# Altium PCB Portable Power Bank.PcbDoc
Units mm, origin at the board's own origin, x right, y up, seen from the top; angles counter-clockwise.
Board outline 51 x 35 mm, 2 copper layers (Top Layer, Bottom Layer); 57 components, 43 nets, 200 pads, 71 vias.
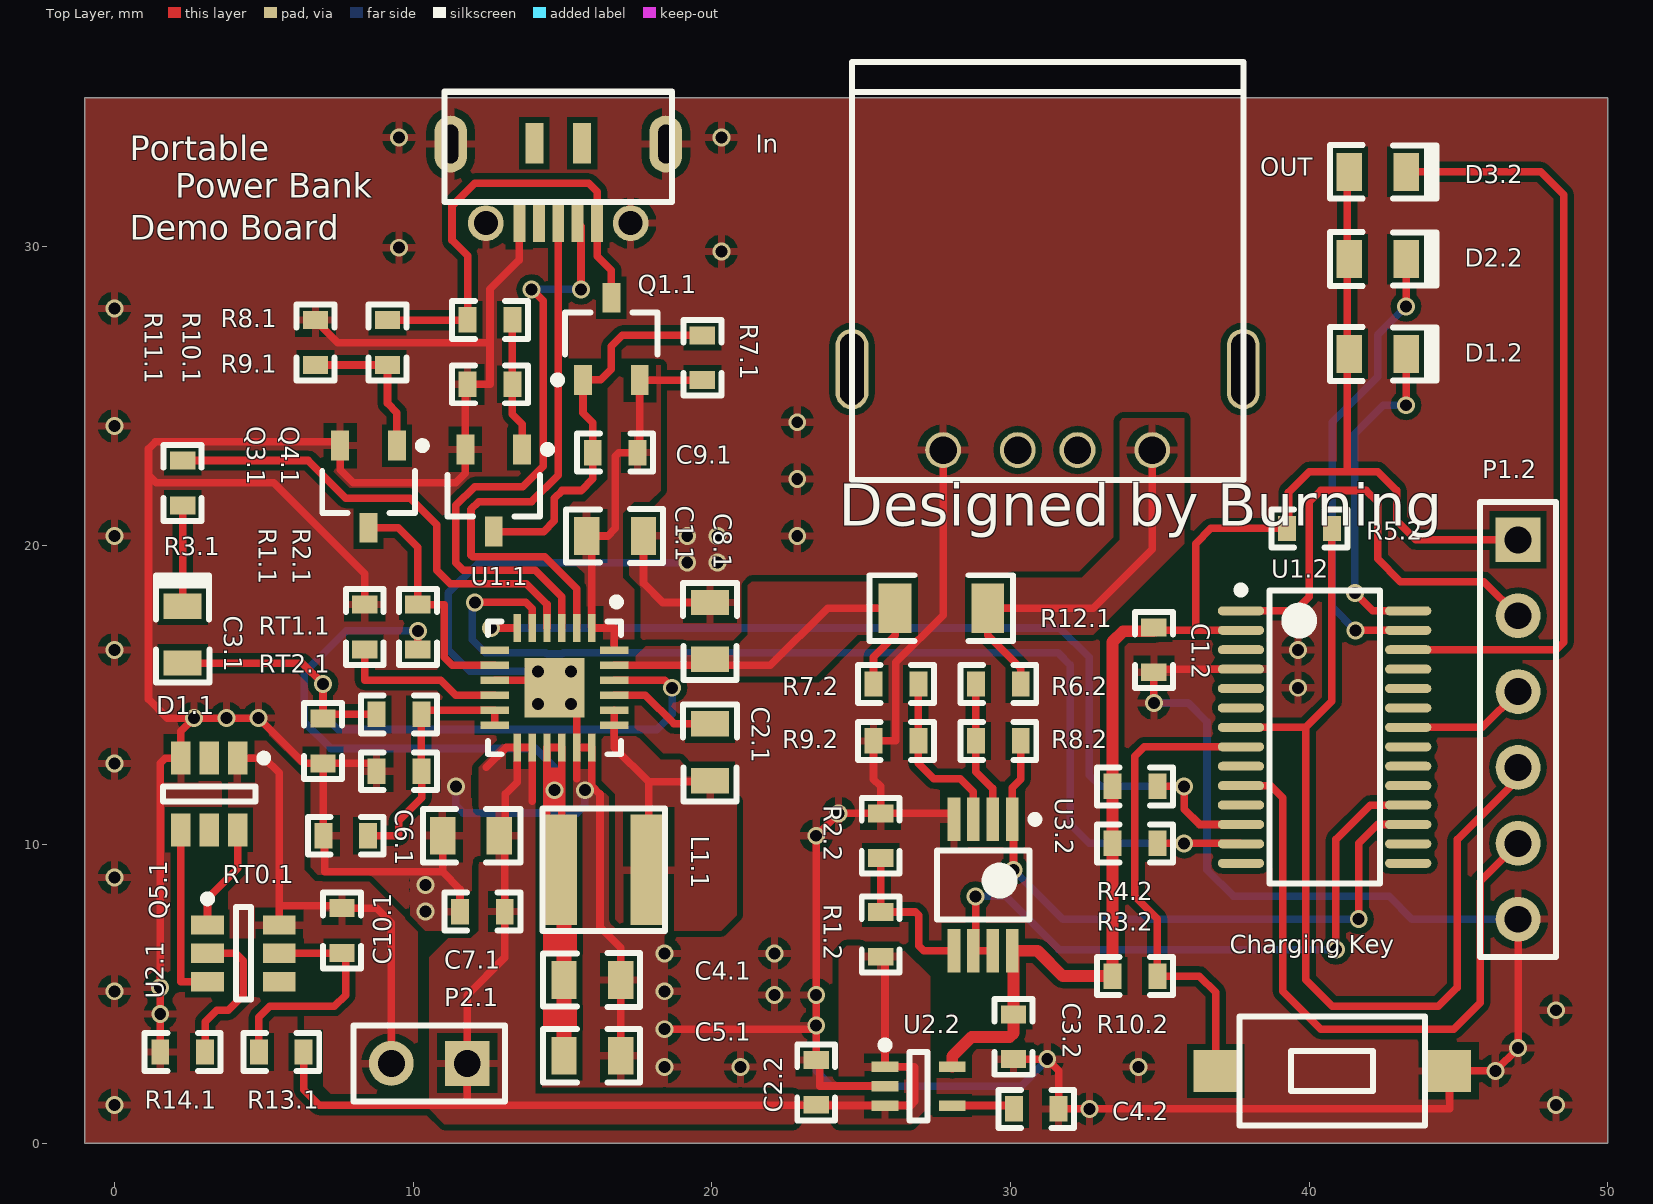
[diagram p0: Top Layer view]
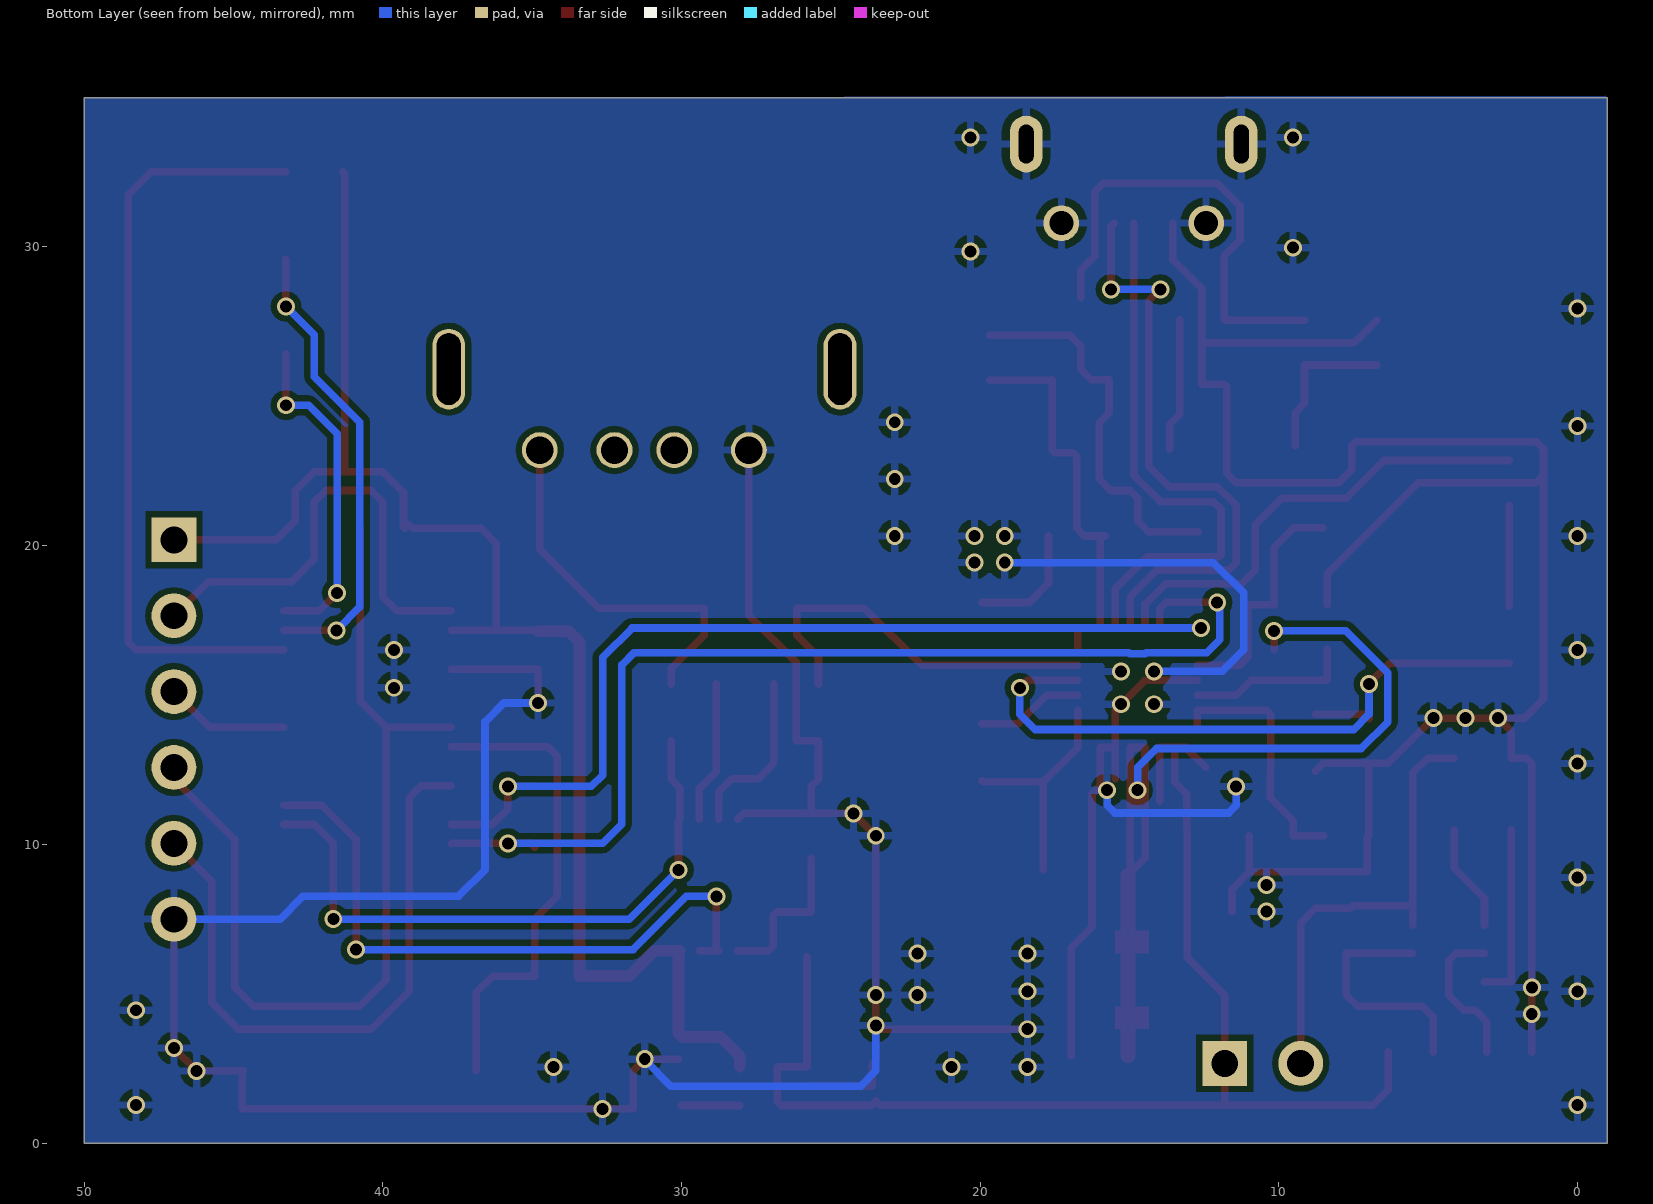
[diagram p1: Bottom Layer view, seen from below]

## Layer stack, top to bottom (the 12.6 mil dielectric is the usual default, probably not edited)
Top Solder: solder mask 0.0102, Solder Resist, Dk 3.5
Top Layer: signal copper 0.0356
Dielectric 1: dielectric 0.32, FR-4, Dk 4.8
Bottom Layer: signal copper 0.0356
Bottom Solder: solder mask 0.0102, Solder Resist, Dk 3.5

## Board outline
-1,0 -1,35 50,35 50,0

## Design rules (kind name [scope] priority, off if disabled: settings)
Clearance [All] p1: gap=0.2
PolygonConnect [All] p1: connectstyle=Relief reliefconductorwidth=0.254 reliefentries=4 polygonreliefangle="90 Angle" airgapwidth=0.254
RoutingVias [All] p1: holewidth=0.711 width=1.27 viastyle="Through Hole" minholewidth=0.711 minwidth=1.27 maxholewidth=0.711 maxwidth=1.27
SolderMaskExpansion [All] p1: expansion=0.102
Width [All] p1: maxlimit=1 minlimit=0.254 preferedwidth=0.254
30 further rules are at their usual default settings.

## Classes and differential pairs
component class "Portable Power Source": C1.1 C2.1 C3.1 C4.1 C5.1 C6.1 C7.1 C8.1 C9.1 C10.1 D1.1 In L1.1 P2.1 Q1.1 Q3.1 Q4.1 Q5.1 R1.1 R2.1 R3.1 R7.1 R8.1 R9.1 R10.1 R11.1 R12.1 R13.1 R14.1 RT0.1 RT1.1 RT2.1 U1.1 U2.1

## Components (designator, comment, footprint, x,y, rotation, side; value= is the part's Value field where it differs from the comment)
C1.1 "0603" D0805 16.764,20.32 r180 top (schematic designator C1)
C1.2 "0603" D0603 34.798,16.51 r90 top (schematic designator C1)
C2.1 "0603" D0805 19.939,13.081 r270 top (schematic designator C2)
C2.2 "0603" D0603 23.495,2.032 r270 top (schematic designator C2)
C3.1 "0603" D0603 6.985,13.462 r90 top (schematic designator C3)
C3.2 "0603" D0603 30.099,3.556 r90 top (schematic designator C3)
C4.1 "0805" D0805 16.002,5.461 r180 top (schematic designator C4)
C4.2 "0603" D0603 30.861,1.143 r180 top (schematic designator C4)
C5.1 "0805" D0805 16.002,2.921 r180 top (schematic designator C5)
C6.1 "0805" D0805 11.938,10.287 r0 top (schematic designator C6)
C7.1 "0603" D0603 12.319,7.747 r0 top (schematic designator C7)
C8.1 "0805" D0805 19.939,17.145 r270 top (schematic designator C8)
C9.1 "0603" D0603 16.764,23.114 r180 top (schematic designator C9)
C10.1 "0603" D0603 7.62,7.112 r270 top (schematic designator C10)
"Charging Key" "Charging Key" SW_A 40.767,2.413 r0 top (schematic designator S1)
D1.1 "0603/0805" D0805_Diode 2.286,17.018 r90 top (schematic designator D1)
D1.2 "0603/0805" D0805_Diode 42.291,26.416 r0 top (schematic designator D1)
D2.2 "0603/0805" D0805_Diode 42.291,29.591 r0 top (schematic designator D2)
D3.2 "0603/0805" D0805_Diode 42.291,32.512 r0 top (schematic designator D3)
In "Power" Micro.Horn 14.859,32.131 r0 top (schematic designator P1)
L1.1 "Inductor" INDUCTOR.4040 16.383,9.144 r180 top (schematic designator L1)
OUT "USB Female" "USB Female" 31.242,25.908 r180 top (schematic designator P0)
P1.2 "BSL Program Interface" HDR1X6 46.99,20.193 r270 top (schematic designator P1)
P2.1 "Battery" HDR1X2 11.811,2.667 r180 top (schematic designator P2)
Q1.1 "AO3401" SOT23 16.637,26.924 r90 top (schematic designator Q1)
Q3.1 "Si2312" SOT23 8.509,21.971 r270 top (schematic designator Q3)
Q4.1 "Si2312" SOT23 12.7,21.844 r270 top (schematic designator Q4)
Q5.1 "FS8205" SOT23-6_N 3.175,11.684 r270 top (schematic designator Q5)
R1.1 "0603" D0603 8.382,17.272 r270 top (schematic designator R1)
R1.2 "0603" D0603 25.654,6.985 r270 top (schematic designator R1)
R2.1 "0603" D0603 10.16,17.272 r270 top (schematic designator R2)
R2.2 "0603" D0603 25.654,10.287 r270 top (schematic designator R2)
R3.1 "0603" D0603 2.286,22.098 r270 top (schematic designator R3)
R3.2 "0603" D0603 34.163,10.033 r180 top (schematic designator R3)
R4.2 "0603" D0603 34.163,11.938 r180 top (schematic designator R4)
R5.2 "0603" D0603 40.005,20.574 r0 top (schematic designator R5)
R6.2 "0603" D0603 29.591,15.367 r0 top (schematic designator R6)
R7.1 "0603" D0603 19.685,26.289 r90 top (schematic designator R7)
R7.2 "0603" D0603 26.162,15.367 r0 top (schematic designator R7)
R8.1 "0603" D0603 12.573,27.559 r180 top (schematic designator R8)
R8.2 "0603" D0603 29.591,13.462 r0 top (schematic designator R8)
R9.1 "0603" D0603 12.573,25.4 r0 top (schematic designator R9)
R9.2 "0603" D0603 26.162,13.462 r0 top (schematic designator R9)
R10.1 "0603" D0603 9.144,26.797 r90 top (schematic designator R10)
R10.2 "0603" D0603 34.163,5.588 r0 top (schematic designator R10)
R11.1 "0603" D0603 6.731,26.797 r270 top (schematic designator R11)
R12.1 "2512" D1206 27.686,17.907 r180 top (schematic designator R12)
R13.1 "0603" D0603 5.588,3.048 r180 top (schematic designator R13)
R14.1 "0603" D0603 2.286,3.048 r0 top (schematic designator R14)
RT0.1 "0603" D0603 7.747,10.287 r0 top (schematic designator RT0)
RT1.1 "0603" D0603 9.525,14.351 r180 top (schematic designator RT1)
RT2.1 "0603" D0603 9.525,12.446 r0 top (schematic designator RT2)
U1.1 "bq24195" QFN24 14.732,15.24 r270 top (schematic designator U1)
U1.2 "MSP430F21x2" TSSOP28 40.513,13.589 r0 top (schematic designator U1)
U2.1 "DW01" SOT23-6_N 4.318,6.35 r0 top (schematic designator U2)
U2.2 "RT9193" SC70-5 26.924,1.905 r0 top (schematic designator U2)
U3.2 "TLV342" TSSOP8 29.083,8.636 r270 top (schematic designator U3)

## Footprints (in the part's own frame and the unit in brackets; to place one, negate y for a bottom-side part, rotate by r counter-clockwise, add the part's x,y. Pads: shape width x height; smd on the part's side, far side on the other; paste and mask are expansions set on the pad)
D0603 [mm] "D0603"
  rect 0.6x0.85 smd: 1(-0.75,0) 2(0.75,0)
  silkscreen extent -1.27,-0.64 1.27,0.64, body extent -0.8,-0.4 0.8,0.4, height 0.5
D0805 [mm] "D0805"
  rect 0.85x1.27 smd: 1(-0.95,0) 2(0.95,0)
  silkscreen extent -1.6,-0.9 1.65,0.9, body extent -1,-0.64 1,0.64, height 1.25
D0805_Diode [mm] "D0805 Diode"
  rect 0.85x1.27 smd: 1(-0.95,0) 2(0.95,0)
  silkscreen extent -1.6,-0.99 1.97,0.99, body extent -1,-0.64 1,0.64, height 1.25
D1206 [mm] "D1206"
  rect 1.1x1.65 smd: 1(-1.55,0) 2(1.55,0)
  silkscreen extent -2.4,-1.1 2.4,1.1, body extent -1.6,-0.8 1.6,0.8, height 1.1
HDR1X2 [mm] "Connector; Header; 2 Position"
  rect 1.5x1.5 hole 0.9: 1(0,0)
  round 1.5 hole 0.9: 2(2.54,0)
  silkscreen extent -1.27,-1.27 3.81,1.27
HDR1X6 [mm] "Connector; Header; 6 Position"
  rect 1.5x1.5 hole 0.9: 1(0,0)
  round 1.5 hole 0.9: 2(2.54,0) 3(5.08,0) 4(7.62,0) 5(10.16,0) 6(12.7,0)
  silkscreen extent -1.27,-1.27 13.97,1.27
INDUCTOR.4040 [mm]
  rect 1.2x3.7 smd mask+0.05: 1(-1.5,0) 2(1.5,0)
  silkscreen extent -2.05,-2.05 2.05,2.05
Micro.Horn [mm]
  oval 1.1x1.9 hole 0.5 slot 1.3 at 90 deg: 0(-3.6,1.313) 0(3.6,1.313)
  round 1.2 hole 0.8: 0(-2.425,-1.337) 0(2.425,-1.337)
  rect 0.6x1.35 smd: 0(-0.8,1.338) 0(0.8,1.338)
  rect 0.4x1.25 smd: 1(1.3,-1.337) 2(0.65,-1.337) 3(0,-1.337) 4(-0.65,-1.337) 5(-1.3,-1.337)
  silkscreen extent -3.81,-0.64 3.81,3.06
QFN24 [mm] "QFN, 24-Leads, Body 4.00x4.00mm, Pitch 0.50mm, Thermal Pad 2.70x2.70mm, IPC Low Density"
  rect 0.95x0.25 smd: 1(-2,1.25) 2(-2,0.75) 3(-2,0.25) 4(-2,-0.25) 5(-2,-0.75) 6(-2,-1.25) 13(2,-1.25) 14(2,-0.75) 15(2,-0.25) 16(2,0.25) 17(2,0.75) 18(2,1.25)
  rect 0.25x0.95 smd: 7(-1.25,-2) 8(-0.75,-2) 9(-0.25,-2) 10(0.25,-2) 11(0.75,-2) 12(1.25,-2) 19(1.25,2) 20(0.75,2) 21(0.25,2) 22(-0.25,2) 23(-0.75,2) 24(-1.25,2)
  rect 2x2 smd: 25(0,0)
  silkscreen extent -3,-2.22 2.22,2.23, body extent -2.08,-2.07 2.07,2.08, height 1
SC70-5 [mm] "SC70, 5-Leads, Body 2.03x2.13mm, Pitch 0.65mm, IPC Medium Density"
  rect 0.9x0.35 smd: 1(-1.125,0.65) 2(-1.125,0) 3(-1.125,-0.65) 4(1.125,-0.65) 5(1.125,0.65)
  silkscreen extent -1.25,-1.15 0.3,1.5, body extent -0.67,-1.12 0.67,1.13, height 1.1
SOT23 [mm] "SOT23, 3-Leads, Body 2.90x2.80mm, Pitch 0.95mm, IPC Medium Density"
  rect 1x0.6 smd: 1(-1.375,0.95) 2(1.375,0) 3(-1.375,-0.95)
  silkscreen extent -1.5,-1.55 0.87,1.92, body extent -0.88,-1.52 0.87,1.53, height 1.45
SOT23-6_N [mm] "SOT23, 6-Leads, Body 2.9x1.6mm, Pitch 0.95mm, Lead Span 2.7mm, IPC Medium Density"
  rect 1.1x0.65 smd: 1(-1.2,0.95) 2(-1.2,0) 3(-1.2,-0.95) 4(1.2,-0.95) 5(1.2,0) 6(1.2,0.95)
  silkscreen extent -1.32,-1.55 0.25,1.95, body extent -0.9,-1.55 0.9,1.55, height 1.45
SW_A [mm] "SMA Switch"
  rect 1.5x1.4 smd mask+0.05: 1(-3.9,0) 2(3.9,0)
  silkscreen extent -3.1,-1.83 3.1,1.83, body extent -3.1,-1.83 3.1,1.83, height 2
TSSOP8 [mm] "TSOP, 8-Leads, Body 3.00x3.00mm, Pitch 0.65mm, IPC Medium Density"
  rect 1.45x0.42 smd: 1(-2.2,0.975) 2(-2.2,0.325) 3(-2.2,-0.325) 4(-2.2,-0.975) 5(2.2,-0.975) 6(2.2,-0.325) 7(2.2,0.325) 8(2.2,0.975)
  silkscreen extent -2.32,-1.55 1.15,1.86, body extent -1.55,-1.55 1.55,1.55, height 1.1
TSSOP28 [mm] "TSOP, 28-Leads, Body 9.70x4.40mm, Pitch 0.65mm, IPC High Density"
  oval 1.55x0.3 smd: 1(-2.8,4.225) 2(-2.8,3.575) 3(-2.8,2.925) 4(-2.8,2.275) 5(-2.8,1.625) 6(-2.8,0.975) 7(-2.8,0.325) 8(-2.8,-0.325) 9(-2.8,-0.975) 10(-2.8,-1.625) 11(-2.8,-2.275) 12(-2.8,-2.925) 13(-2.8,-3.575) 14(-2.8,-4.225) 15(2.8,-4.225) 16(2.8,-3.575) 17(2.8,-2.925) 18(2.8,-2.275) 19(2.8,-1.625) 20(2.8,-0.975) 21(2.8,-0.325) 22(2.8,0.325) 23(2.8,0.975) 24(2.8,1.625) 25(2.8,2.275) 26(2.8,2.925) 27(2.8,3.575) 28(2.8,4.225)
  silkscreen extent -2.92,-4.9 1.85,5.05, body extent -2.25,-4.9 2.25,4.9, height 1.2
"USB Female" [mm]
  round 1.2 hole 0.92 mask+0.05: 1(-3.5,2.71) 2(-1,2.71) 3(1,2.71) 4(3.5,2.71)
  oval 1.1x2.7 hole 0.8 slot 2.4 at 90 deg mask+0.05: 5(-6.55,0) 5(6.55,0)
  silkscreen extent -6.55,-10.28 6.55,3.71

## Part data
C1.1 C1.2 C2.1 C2.2 C3.1 C3.2 C4.1 C4.2 C5.1 C6.1 C7.1 C8.1 C9.1 C10.1: library part Cap, "Capacitor"
"Charging Key": library part SW-PB, "Switch"
D1.1 D1.2 D2.2 D3.2: library part LED0, "Typical INFRARED GaAs LED"
In: library part "Micro USB Horn", "MIcro USB Connector Horn"
P1.2: library part "Header 6", "Header, 6-Pin"
P2.1: library part "Header 2", "Header, 2-Pin"
Q1.1: "AO3401 P-Channel MOSFET"
Q3.1 Q4.1: "SI2312 N-Channel MOSFEt"
Q5.1: "FS8205 Dual MOS"
R1.1 R1.2 R2.1 R2.2 R3.1 R3.2 R4.2 R5.2 R6.2 R7.1 R7.2 R8.1 R8.2 R9.1 R9.2 R10.1 R10.2 R11.1 R12.1 R13.1 R14.1 RT0.1 RT1.1 RT2.1: library part Res1, "Resistor"
U1.1: "A Battery charger manager published by Ti"
U1.2: library part MSP430F21x2_PW, "MSP430F21x2_PW"
U2.1: "Battery Protector"
U2.2: "3V3 Voltage Regulator"
U3.2: library part LPV358, "LPV358 Op Amp"

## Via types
v1: diameter 0.6, hole 0.4, Top Layer to Bottom Layer, 71 vias

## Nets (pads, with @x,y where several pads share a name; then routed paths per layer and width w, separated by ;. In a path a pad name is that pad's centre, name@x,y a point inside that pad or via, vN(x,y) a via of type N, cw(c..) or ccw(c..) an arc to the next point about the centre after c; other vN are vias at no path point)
3V3: C1.2.2 C3.2.2 D1.2.1 D2.2.1 D3.2.1 P1.2.1 R3.2.2 R4.2.2 R5.2.1 R10.2.1 U1.2.2 U2.2.5 U3.2.8 | length 51.7
  Top Layer w0.254: U3.2.8 U3.2.8@30.099,6.395 ; C1.2.2@34.798,17.133 34.829,17.164 36.195,17.164 ; U1.2.2 36.195,17.164 ; R5.2.1@39.128,20.701 39.001,20.574 36.703,20.574 36.195,20.066 36.195,17.164 ; R5.2.1 39.306,20.626 39.306,21.78 40.005,22.479 41.275,22.479 ; D3.2.1 41.275,32.446 41.275,22.479 ; P1.2.1 43.561,20.193 42.926,20.828 42.926,21.844 42.291,22.479 41.275,22.479
  Top Layer w0.4: U2.2.5 28.049,2.903 28.702,3.556 29.972,3.556 30.099,3.683 C3.2.2 U3.2.8@30.099,6.395 ; U3.2.8 30.902,6.436 31.75,5.588 R10.2.1 R4.2.2 33.413,16.776 33.77,17.133 C1.2.2@34.798,17.133
ADC_B: U1.2.18 U3.2.6 U3.2.7 | length 21.9
  Top Layer w0.254: v1(28.829,8.255) 28.829,6.507 U3.2.6 U3.2.7 ; v1(40.894,6.477) 40.894,10.16 42.048,11.314 U1.2.18
  Bottom Layer w0.254: v1(28.829,8.255) 29.845,8.255 31.623,6.477 v1(40.894,6.477)
ADC_L: R8.2.2 U1.2.17 U3.2.1 | length 21.2
  Top Layer w0.254: v1(30.099,9.144) 30.099,10.795 U3.2.1 30.058,11.897 30.341,12.18 R8.2.2 ; v1(41.656,7.493) 41.656,10.033 42.287,10.664 U1.2.17
  Bottom Layer w0.254: v1(30.099,9.144) 31.75,7.493 v1(41.656,7.493)
BAT: C2.2.2 C6.1.2 C7.1.2 P2.1.1 R1.2.2 R13.1.1 U1.1.13 U1.1.14 U2.2.1 U2.2.3 | length 44.2
  Top Layer w0.254: R13.1.1 6.338,1.79 6.858,1.27 11.811,1.27 ; 12.446,12.573 13.113,13.24 U1.1.13 ; 13.982,11.442 U1.1.14 U1.1.13 ; R1.2.2@25.799,6.235 U2.2.1 26.782,2.555 26.797,2.54 26.797,1.397 26.655,1.255 U2.2.3 23.649,1.255 23.495,1.409 23.356,1.27 11.811,1.27 ; 11.811,1.27 P2.1.1 11.811,4.953 13.069,6.211 C7.1.2 13.069,10.468 13.081,10.48 13.081,11.684 13.482,12.085 U1.1.13
D+: In.3 U1.1.2 | length 18.7
  Top Layer w0.254: In.3 14.859,22.359 13.963,21.463 12.192,21.463 11.938,21.209 11.938,19.685 11.991,19.632 14.404,19.632 15.482,18.554 U1.1.2
D-: In.2 U1.1.3 | length 20.4
  Top Layer w0.254: v1(13.97,28.575) 14.351,28.194 14.351,22.658 13.664,21.971 12.058,21.971 11.43,21.343 11.43,19.431 11.683,19.178 14.096,19.178 14.982,18.292 U1.1.3 ; In.2 15.621,30.681 v1(15.621,28.575)
  Bottom Layer w0.254: v1(13.97,28.575) v1(15.621,28.575)
GND: "Charging Key.2" C1.1.1 C1.2.1 C2.2.1 C3.1.1 C3.2.1 C4.1.1 C4.2.1 C5.1.1 C6.1.1 C7.1.1 C8.1.1 In.0@11.259,33.444 In.0@12.434,30.794 In.0@17.284,30.794 In.0@18.459,33.444 In.5 OUT.4 P1.2.6 Q3.1.3 Q4.1.3 Q5.1.3 R1.1.1 R2.2.1 R9.1.1 R9.2.1 R11.1.1 R14.1.1 RT0.1.1 RT2.1.1 U1.1.9 U1.1.17 U1.1.18 U1.1.25 U1.2.4 U2.2.2 U3.2.4 | length 206.9
  Top Layer w0.254: R14.1.1 1.536,12.712 1.708,12.884 Q5.1.3 2.225,13.782 v1(2.667,14.224) ; R11.1.1 7.481,26.797 12.573,26.797 ; R1.1.1 8.382,19.05 5.334,22.098 1.397,22.098 1.143,22.352 ; RT2.1.1 8.509,12.712 C3.1.1 ; C6.1.1 10.988,9.078 ; C7.1.1 11.569,8.497 10.988,9.078 ; U1.1.9 14.482,15.49 U1.1.25 v1(15.282,14.69) ; In.5 13.559,29.561 12.573,28.575 12.573,26.797 ; 15.482,12.204 U1.1.17 ; U1.1.25@15.482,14.49 U1.1.17 ; C5.1.1 C4.1.1 16.952,6.543 16.256,7.239 16.256,11.684 15.982,11.958 U1.1.18 U1.1.17 ; C1.1.1 17.714,18.735 18.354,18.095 C8.1.1 ; v1(18.415,3.81) 23.368,3.81 v1(23.495,3.937) ; U2.2.2 25.799,1.909 23.618,1.909 23.618,2.659 C2.2.1 v1(23.495,3.937) ; OUT.4 27.742,17.676 26.162,16.096 26.162,13.462 R9.2.1 25.412,12.18 25.654,11.938 R2.2.1 ; U3.2.4 27.907,11.037 R2.2.1 ; C3.2.1 v1(31.23,2.806) 31.611,2.425 C4.2.1 v1(32.639,1.143) 44.704,1.143 44.704,2.376 44.667,2.413 v1(46.228,2.413) v1(46.99,3.175) P1.2.6 ; v1(34.798,14.732) C1.2.1 ; C1.2.1@34.798,15.864 U1.2.4 ; 1.143,22.352 1.143,14.859 1.778,14.224 v1(2.667,14.224) ; 1.143,22.352 1.143,23.241 1.377,23.475 7.43,23.475 Q3.1.3 7.559,22.54 8.001,22.098 11.43,22.098 11.75,22.418 Q4.1.3 11.75,25.327 R9.1.1 12.573,25.4 12.573,26.797 ; v1(2.667,14.224) v1(3.746,14.224) v1(4.826,14.224) 6.338,12.712 C3.1.1 ; C3.1.1 6.997,12.7 RT0.1.1 7.046,10.238 7.046,9.078 10.988,9.078 ; v1(23.495,3.937) v1(23.495,4.953) v1(23.495,10.287) v1(24.245,11.037) R2.2.1
  Bottom Layer w0.254: v1(11.43,11.938) 11.43,11.303 11.684,11.049 15.494,11.049 15.748,11.303 v1(15.748,11.811) ; v1(14.182,15.79) 11.896,15.79 11.176,16.51 11.176,18.415 12.192,19.431 v1(19.177,19.431) ; v1(23.495,3.937) 23.495,2.413 24.003,1.905 30.353,1.905 31.23,2.782 v1(31.23,2.806) ; v1(34.798,14.732) 35.941,14.732 36.576,14.097 36.576,9.144 37.465,8.255 42.672,8.255 43.434,7.493 P1.2.6
  other v1: 0,1.27 48.26,1.27 18.415,2.54 20.955,2.54 34.29,2.54 1.536,4.318 48.26,4.445 22.098,4.953 0,5.08 18.415,5.08 1.524,5.207 18.415,6.35 22.098,6.35 10.414,7.747 10.414,8.636 0,8.89 0,12.7 14.182,14.69 39.624,15.24 15.282,15.79 0,16.51 39.624,16.51 20.193,19.431 0,20.32 19.177,20.32 20.193,20.32 22.86,20.32 22.86,22.225 0,24.003 22.86,24.13 0,27.94 20.32,29.845 9.525,29.972 9.525,33.655 20.32,33.655
INT: U1.1.7
KEY: "Charging Key.1" R10.2.2 U1.2.8 | length 16.2
  Top Layer w0.254: 36.867,2.413 36.867,5.043 36.322,5.588 R10.2.2 34.913,7.505 34.163,8.255 34.163,12.954 34.473,13.264 U1.2.8
LED1: D1.2.2 U1.2.28 | length 11.2
  Top Layer w0.254: v1(41.529,18.415) 42.13,17.814 U1.2.28 ; v1(43.241,24.699) D1.2.2
  Bottom Layer w0.254: v1(41.529,18.415) 41.529,23.749 42.479,24.699 v1(43.241,24.699)
LED2: D2.2.2 U1.2.27 | length 15.5
  Top Layer w0.254: v1(41.548,17.164) U1.2.27 ; v1(43.241,28.006) D2.2.2
  Bottom Layer w0.254: v1(41.548,17.164) 40.767,17.945 40.767,24.13 42.291,25.654 42.291,27.056 v1(43.241,28.006)
LED3: D3.2.2 U1.2.26 | length 25.9
  Top Layer w0.254: D3.2.2 47.752,32.512 48.514,31.75 48.514,16.764 48.264,16.514 U1.2.26
NetC1.1_2: C1.1.2 C9.1.1 Q1.1.3 R7.1.1 U1.1.1 U1.1.24 | length 13.3
  Top Layer w0.254: C1.1.2 16.51,20.32 16.764,20.574 16.764,22.987 16.891,23.114 C9.1.1 17.587,23.187 Q1.1.3 17.597,25.539 R7.1.1 ; C1.1.2@15.982,20.152 U1.1.1 16.732,17.24 U1.1.24
NetC2.1_1: C2.1.1 U1.1.21 | length 3.6
  Top Layer w0.254: U1.1.21 17.776,14.99 18.735,14.031 C2.1.1
NetC2.1_2: C2.1.2 L1.1.1 U1.1.19 U1.1.20 | length 7.9
  Top Layer w0.254: U1.1.20 U1.1.19 16.732,13.24 17.883,12.089 ; L1.1.1 17.883,12.089 ; C2.1.2 19.897,12.089 17.883,12.089
NetC4.2_2: C4.2.2 U2.2.4 | length 1.9
  Top Layer w0.254: U2.2.4 C4.2.2@29.999,1.255
NetC8.1_2: C8.1.2 R7.2.1 R12.1.2 U1.1.23 | length 13
  Top Layer w0.254: U1.1.23 21.959,15.99 23.876,17.907 R12.1.2 26.136,16.992 25.412,16.268 R7.2.1
NetC9.1_2: C9.1.2 Q1.1.1 Q4.1.2 R7.1.2 | length 13
  Top Layer w0.254: Q4.1.2 14.373,20.469 14.732,20.828 14.732,21.59 14.986,21.844 15.621,21.844 16.014,22.237 C9.1.2 16.014,24.118 15.687,24.445 Q1.1.1 16.278,25.549 16.637,25.908 16.637,26.67 17.006,27.039 R7.1.2
NetC10.1_1: C10.1.1 P2.1.2 Q5.1.1 U2.1.6 | length 15.4
  Top Layer w0.254: Q5.1.1 5.023,12.884 5.518,12.389 5.518,7.944 ; U2.1.6 5.518,7.944 ; P2.1.2 9.271,7.366 8.775,7.862 C10.1.1 7.538,7.944 5.518,7.944
NetC10.1_2: C10.1.2 R13.1.2 U2.1.5 | length 8
  Top Layer w0.254: R13.1.2 4.838,4.203 5.207,4.572 7.366,4.572 7.747,4.953 7.747,6.362 7.735,6.35 U2.1.5
NetD1.1_2: D1.1.2 R3.1.2 | length 3.4
  Top Layer w0.254: D1.1.2 R3.1.2
NetP0.3_1: OUT.1 R6.2.2 R12.1.1 | length 12.6
  Top Layer w0.254: R6.2.2 30.341,15.887 29.236,16.992 R12.1.1 32.766,17.907 34.742,19.883 OUT.1
NetP1.1_1: In.1 Q1.1.2 R8.1.2 R10.1.2 | length 15.7
  Top Layer w0.254: R10.1.2 11.811,27.547 R8.1.2 11.823,29.706 11.303,30.226 11.303,31.369 12.065,32.131 15.875,32.131 16.159,31.847 In.1 16.159,29.688 16.637,29.21 Q1.1.2
NetQ3.1_1: Q3.1.1 R10.1.1 R11.1.2 | length 5.2
  Top Layer w0.254: R11.1.2 R10.1.1 9.144,24.765 9.459,24.45 Q3.1.1
NetQ3.1_2: Q3.1.2 R2.1.1 U1.1.8 | length 8.3
  Top Layer w0.254: Q3.1.2 9.503,20.596 10.16,19.939 R2.1.1 11.049,18.022 11.049,16.256 11.315,15.99 U1.1.8
NetQ4.1_1: Q4.1.1 R8.1.1 R9.1.2 | length 4.5
  Top Layer w0.254: R8.1.1 R9.1.2 13.323,24.396 13.65,24.069 Q4.1.1
NetQ5.1_4: Q5.1.4 U2.1.3 | length 6
  Top Layer w0.254: Q5.1.4 2.22,10.479 2.22,5.4 U2.1.3
NetQ5.1_6: Q5.1.6 U2.1.1 | length 3.6
  Top Layer w0.254: U2.1.1 3.118,8.198 4.125,9.205 Q5.1.6
NetR1.1_2: R1.1.2 U1.1.10 | length 5.6
  Top Layer w0.254: R1.1.2 8.382,15.494 10.922,15.494 11.426,14.99 U1.1.10
NetR1.2_1: R1.2.1 R2.2.2 U3.2.5 | length 5.4
  Top Layer w0.254: R2.2.2 R1.2.1 26.809,7.735 26.924,7.62 26.924,6.604 27.092,6.436 U3.2.5
NetR6.2_1: R6.2.1 R8.2.1 U3.2.2 | length 4.8
  Top Layer w0.254: R6.2.1 R8.2.1 28.841,12.434 29.408,11.867 U3.2.2
NetR7.2_2: R7.2.2 R9.2.2 U3.2.3 | length 5.8
  Top Layer w0.254: R7.2.2 R9.2.2 26.912,12.712 27.432,12.192 28.321,12.192 28.758,11.755 U3.2.3
NetR14.1_2: R14.1.2 U2.1.2 | length 5.1
  Top Layer w0.254: R14.1.2 3.036,4.052 3.429,4.445 3.81,4.445 4.318,4.953 4.318,6.096 4.064,6.35 U2.1.2
P1.1: P1.2.3 U1.2.22 | length 4.2
  Top Layer w0.254: U1.2.22 45.791,13.914 P1.2.3
P2.2: P1.2.5 U1.2.10 | length 21.4
  Top Layer w0.254: U1.2.10 38.709,11.964 39.116,11.557 39.116,5.08 40.386,3.81 44.831,3.81 45.72,4.699 45.72,8.763 P1.2.5
REGN: C3.1.2 D1.1.1 RT1.1.2 U1.1.22 | length 24
  Top Layer w0.254: D1.1.1 6.284,16.068 v1(6.985,15.367) C3.1.2 7.124,14.351 RT1.1.2 ; U1.1.22 18.419,15.49 v1(18.669,15.24)
  Bottom Layer w0.254: v1(6.985,15.367) 6.985,14.351 7.493,13.843 18.161,13.843 18.669,14.351 v1(18.669,15.24)
RST: P1.2.4 R5.2.2 U1.2.7 | length 31.6
  Top Layer w0.254: U1.2.7 39.878,13.914 ; R5.2.2 40.755,14.791 39.878,13.914 ; P1.2.4 46.99,12.192 44.958,10.16 44.958,5.207 44.323,4.572 40.767,4.572 39.878,5.461 39.878,13.914
SCL: R3.2.1 U1.1.5 U1.2.13 | length 36.6
  Top Layer w0.254: v1(12.065,18.098) 13.772,18.098 13.982,17.888 U1.1.5 ; R3.2.1@34.913,9.906 35.04,10.033 v1(35.814,10.033) 37.694,10.033 U1.2.13
  Bottom Layer w0.254: v1(12.065,18.098) 11.978,18.01 11.978,16.851 12.412,16.417 14.442,16.417 14.476,16.383 14.988,16.383 15.022,16.417 31.589,16.417 32.004,16.002 32.004,10.668 32.639,10.033 v1(35.814,10.033)
SDA: R4.2.1 U1.1.6 U1.2.12 | length 32.4
  Top Layer w0.254: v1(12.605,17.24) U1.1.6 ; R4.2.1 v1(35.814,11.938) 35.814,11.176 36.326,10.664 U1.2.12
  Bottom Layer w0.254: v1(12.605,17.24) 31.655,17.24 32.639,16.256 32.639,12.319 33.02,11.938 v1(35.814,11.938)
STAT: R3.1.1 U1.1.4 | length 15.9
  Top Layer w0.254: R3.1.1 6.489,22.848 7.747,21.59 9.906,21.59 10.795,20.701 10.795,19.177 11.248,18.724 13.788,18.724 14.482,18.03 U1.1.4
SYS: C4.1.2 C5.1.2 L1.1.2 R2.1.2 U1.1.15 U1.1.16 | length 30.5
  Top Layer w0.254: R2.1.2 v1(10.16,17.145) ; 14.478,11.43 14.478,9.549 L1.1.2 L1.1.2@15.052,8.975 ; 14.482,12.45 U1.1.15 U1.1.16 L1.1.2@14.982,9.243
  Top Layer w0.5: C5.1.2 C4.1.2 L1.1.2@15.052,8.975
  Bottom Layer w0.254: v1(10.16,17.145) 7.757,17.145 6.358,15.746 6.358,14.089 7.239,13.208 14.097,13.208 14.732,12.573 v1(14.732,11.811)
TEST: P1.2.2 U1.2.1 | length 15.7
  Top Layer w0.254: U1.2.1 39.531,17.814 40.005,18.288 40.005,21.463 40.386,21.844 41.91,21.844 42.291,21.463 42.291,19.558 43.053,18.796 45.847,18.796 P1.2.2
TS: RT0.1.2 RT1.1.1 RT2.1.2 U1.1.11 U1.1.12 | length 8.4
  Top Layer w0.254: RT0.1.2 9.525,10.287 9.525,10.795 10.287,11.557 10.287,12.434 RT2.1.2 RT1.1.1 10.414,14.49 U1.1.11 U1.1.12
pads on no net: In.0@14.059,33.469 In.0@15.659,33.469 In.4 OUT.2 OUT.3 OUT.5 Q5.1.2 Q5.1.5 U1.2.3 U1.2.5 U1.2.6 U1.2.9 U1.2.11 U1.2.14 U1.2.15 U1.2.16 U1.2.19 U1.2.20 U1.2.21 U1.2.23 U1.2.24 U1.2.25 U2.1.4

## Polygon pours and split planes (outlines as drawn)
GND on Top Layer "Top Layer-No Net" (solid, remove dead copper, pour order 28): -1,35 -1,0 50,0 50,35
NetP0.3_1 on Top Layer "Top Layer-No Net" (solid, remove dead copper, pour order 26): 28.575,18.923 28.575,17.018 32.766,17.018 35.179,19.431 35.814,20.066 35.814,24.257 33.655,24.257 33.655,20.32 33.655,20.193 32.385,18.923
NetC8.1_2 on Top Layer "Top Layer-No Net" (solid, remove dead copper, pour order 24): 16.256,16.129 16.256,15.875 18.923,15.875 19.177,15.621 23.495,15.621 24.765,16.891 24.892,17.018 26.67,17.018 26.67,18.796 21.336,18.796 21.209,18.669 21.209,17.018 21.082,16.891 20.828,16.637 17.907,16.637 17.78,16.637 17.526,16.383 17.272,16.129
GND on Top Layer "Top Layer-No Net" (solid, remove dead copper, pour order 22): 15.367,13.716 15.367,1.905 18.415,1.905 18.415,6.985 16.51,6.985 16.256,7.239 16.256,11.684 15.982,11.958 15.982,13.696 16.002,13.716
NetC10.1_1 on Top Layer "Top Layer-No Net" (solid, remove dead copper, pour order 20): 3.81,13.462 3.81,6.858 6.35,6.858 6.35,3.81 6.985,3.81 6.985,1.905 7.239,1.651 10.033,1.651 10.287,1.905 10.16,2.032 10.16,6.985 10.16,7.112 8.636,8.636 8.509,8.763 6.731,8.763 6.35,9.144 6.35,12.065 6.35,12.192 5.08,13.462
BAT on Top Layer "Top Layer-No Net" (solid, remove dead copper, pour order 16): 14.097,1.663 14.109,1.651 24.257,1.651 24.257,6.35 24.511,6.604 26.289,6.604 27.051,5.842 27.305,5.588 27.305,1.27 26.67,0.635 11.049,0.635 10.541,1.143 10.541,1.663
GND on Top Layer "Top Layer-No Net" (solid, remove dead copper, pour order 14): 17.272,20.955 17.272,18.923 18.542,17.653 18.542,17.145 18.796,16.891 20.574,16.891 20.701,16.891 20.955,17.145 20.955,20.574 20.955,20.701 20.701,20.955
NetC1.1_2 on Top Layer "Top Layer-No Net" (solid, remove dead copper, pour order 12): 15.113,21.209 15.113,19.685 15.748,19.05 15.748,16.764 16.129,16.764 16.129,16.383 17.272,16.383 17.399,16.51 17.399,18.542 17.018,18.923 17.018,20.828 17.018,21.082 17.399,21.463 17.907,21.463 18.161,21.717 18.288,21.844 18.288,26.035 17.018,26.035 17.018,25.781 16.51,25.273 16.51,22.225 15.748,21.463 15.367,21.463
NetC2.1_2 on Top Layer "Top Layer-No Net" (solid, remove dead copper, pour order 10): 16.256,14.605 16.256,12.192 16.764,11.684 16.764,7.62 16.764,7.493 17.145,7.112 19.685,7.112 20.32,7.112 20.828,7.62 20.828,12.446 20.828,12.7 20.701,12.827 18.288,12.827 17.526,13.589 17.526,14.605
GND on Top Layer "Top Layer-No Net" (solid, remove dead copper, pour order 6): 11.938,12.573 11.938,7.112 11.049,7.112 10.414,7.112 9.906,7.62 9.906,10.668 10.922,11.684 10.922,12.573
BAT on Top Layer "Top Layer-No Net" (solid, remove dead copper, pour order 4): 13.335,13.716 14.097,13.716 14.097,4.064 14.097,1.27 10.541,1.27 10.541,6.223 11.176,6.858 11.938,6.858 12.192,7.112 12.192,12.573
GND on Bottom Layer "Top Layer-No Net" (solid, remove dead copper, pour order 30): -1.016,35.052 -1.016,0.016 -1,0 50,0 50,35

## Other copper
Top Layer:
  rectangle net SYS: 14.351,3.81 15.494,4.572
  rectangle net SYS: 14.351,6.35 15.494,7.112
  rectangle net SYS: 14.351,11.176 14.986,12.573

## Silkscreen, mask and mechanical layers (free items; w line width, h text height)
Top Overlay:
  text "Portable" at 0.508,32.639 h1.4
  text "Power Bank" at 2.032,31.369 h1.4
  text "Demo Board" at 0.508,29.972 h1.4
  text "Designed by Burning" at 24.257,20.193 h2.4
Mechanical 1:
  the board outline again, w0.254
